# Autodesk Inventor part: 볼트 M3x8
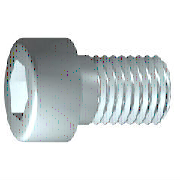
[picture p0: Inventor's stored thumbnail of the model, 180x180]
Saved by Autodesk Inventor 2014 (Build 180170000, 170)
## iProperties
IsCustomPart: 0
Created: 2012-02
Part Number: 볼트 M3x8
Material: 강철, 연강
Description: 6각머리 태핑 나사
Document SubType Name: Modeling
Standard: KS B 1003
Designer: mduedu
Standards Organization: KS
Language: ko-KR
Size Designation: M 3 x 8
Categories: <MemberInstance><Categories><Category DisplayName="조임쇠" InternalName="e4da775c-781d-43d5-af7c-5136215cf5a6" Mnemonic="FSTN"><Category DisplayName="볼트" InternalN
Density: 7.86 g/cm^3
Appearance: 강철
Mass: 0.929844 g
Surface Area: 1.83001 cm^2
Volume: 0.118301 cm^3
Author: mduedu
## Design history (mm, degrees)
sketch "스케치1"
  geometry: L1 (-0.867, 0)-(8, 0); L2 (8, 0)-(8, 1.5); L3 (8, 1.5)-(1.25, 1.5); L4 (1.25, 1.5)-(0.943, 1.5); L5 (0.943, 1.5)-(0, 1.5); L6 (0, 1.5)-(0, 2.75); L7 (0, 2.75)-(-3, 2.75); L8 (-3, 2.75)-(-3, 1.443); L9 (-3, 1.443)-(-1.7, 1.443); L10 (-1.7, 1.443)-(-0.867, 0); L11 (-5.2, 0)-(10.2, 0) reference; L12 (0, -0.55)-(0, 3.3) reference; L13 (1.25, 1.5)-(0, 1.5)
  constraints: 22 end point, 6 parallel, 2 collinear, 2 perpendicular, 1 horizontal, 1 point on line
  dimensions: "d1" = 6.75 distance from line of L3.end L2 (= GEL); "d2" = 0.30683 distance of L4.end L3.end (computed from GAL); "d3" = 3 distance between parallel lines of L8 L6 (= KOH); "d4" = 1.3 distance of L8.end L9.end (= INTI); "d5" = 60 deg angle of L10 L1; "d6" = 3 diameter of L3 L1 (= GD); "d7" = 3 diameter of L5 L1 (= BDM); "d8" = 2.88675 diameter of L9 L1 (= 1.1547 x SW); "d9" = 5.5 diameter of L7 L1 (= KOD); "d26" = 8 distance between parallel lines of L12 L2 (= NLG)
revolve "본체" sketch "스케치1" stored, may be unused: angle "d10" = 90 deg
sketch "스케치2"
  geometry: L1 (0, -3.85)-(0, 3.85) reference; L2 (-3.85, 0)-(3.85, 0) reference; L3 (1.443, 0)-(0.722, -1.25); L4 (0.722, -1.25)-(-0.722, -1.25); L5 (-0.722, -1.25)-(-1.443, 0); L6 (-1.443, 0)-(-0.722, 1.25); L7 (-0.722, 1.25)-(0.722, 1.25); L8 (0.722, 1.25)-(1.443, 0); 2 further points
  constraints: 12 end point, 1 coincident, 1 horizontal alignment, 1 point on line, 12 other
extrude "슬롯" join sketch "스케치2" stored distance "d11" = 10; taper "d12" = 0 deg
workplane "Work Plane1"
fillet "Fillet2" dims "d30" = 0.1 (= R)
body "Solid1"
fillet "모깎기1" dims "d17" = 0.3 (= RR)
feature "스레드" dims "d13" = 6.75 (= GEL), "d14" = 0
chamfer "모따기1" distance "d15" = 0.30673 (= -0.5 x SPD + 0.5 x GD); stored, may be unused: second distance "d16" = 0.30673 (= GUL), angle "d27" = 45 deg
other parameters: "GD" = 3 (= NND) [user parameter; used in 2 equation terms], "NLG" = 8 [user parameter; used in 1 equation term], "GEL" = 6.75 [user parameter; used in 2 equation terms], "KOD" = 5.5 [user parameter; used in 1 equation term], "KOH" = 3 [user parameter; used in 1 equation term], "INTI" = 1.3 [user parameter; used in 1 equation term], "GAL" = 0.30673 (= 0.61345 x PTC) [user parameter; used in 1 equation term], "GUL" = 0.30673 (= 0.61345 x PTC) [user parameter; used in 1 equation term], "BDM" = 3 (= NND) [user parameter; used in 1 equation term], "SW" = 2.5 [user parameter; used in 2 equation terms], "RR" = 0.3 [user parameter; used in 1 equation term], "SPD" = 2.38655 (= NND - 1.2269 x PTC) [user parameter; used in 1 equation term], "d19" = 0, "d28" = 0, "d29" = 0, "R" = 0.1 [user parameter; used in 1 equation term], "PHH" = 0.1 [user parameter], "GD1" = 2.38655 (= THREADDIA - 1.2269 x PTC) [user parameter], "THREADDIA" = 3 [user parameter; used in 1 equation term], "FAWI" = 45 deg [user parameter], "PTC" = 0.5 [user parameter; used in 5 equation terms], "NND" = 3 [user parameter; used in 3 equation terms], "TOA" = 30 deg [user parameter], "E0" = 2.8875 (= 1.155 x SW) [user parameter]
